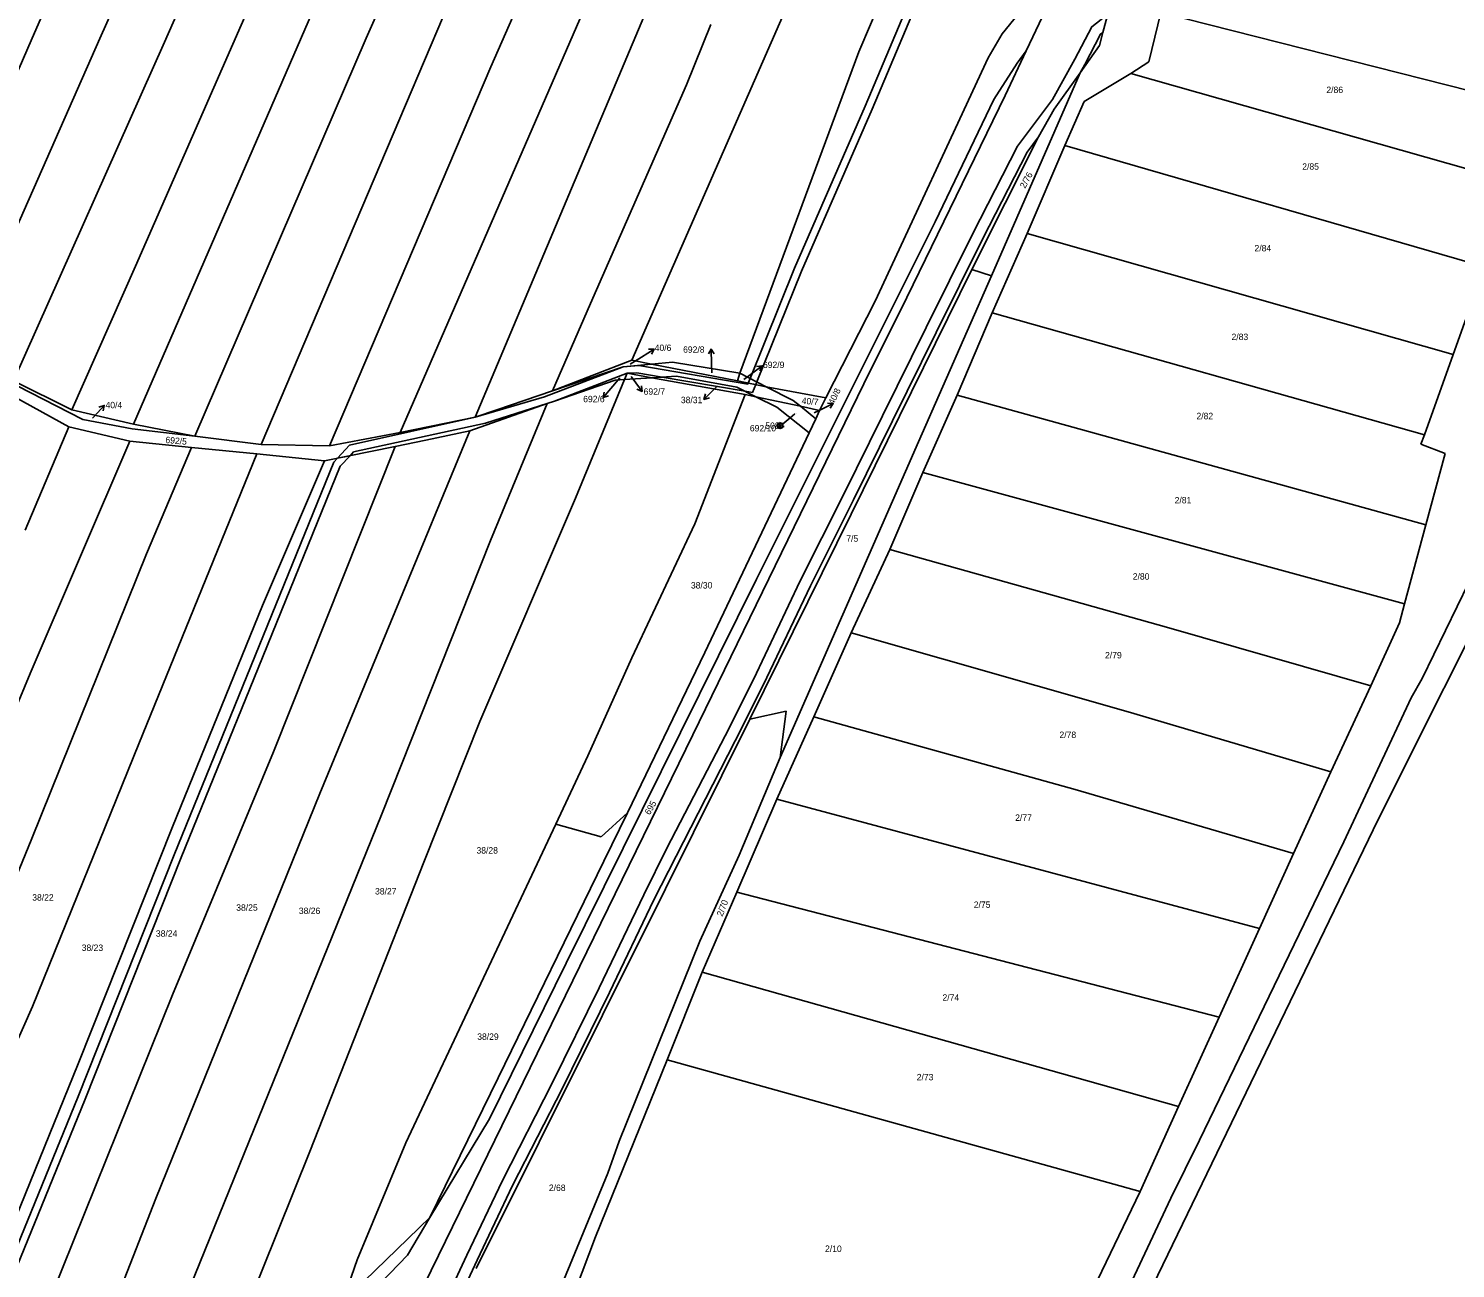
# Model space of a CAD drawing. Extents: x -747333 to -745433, y -1133152 to -1130600.
# Drawn here: x -746124.2 to -745745.7, y -1131253.3 to -1130924.3 of the extents above; entities that cross this region are included whole.
import ezdxf

# ---------------------------------------------------------------- set-up
doc = ezdxf.new("R2010")
doc.units = 0
for name, color, linetype in [('Vrstva 1', 7, 'Continuous'), ('Vrstva 10', 7, 'Continuous'), ('Vrstva 16', 7, 'Continuous'), ('Vrstva 17', 7, 'Continuous'), ('Vrstva 18', 7, 'Continuous'), ('Vrstva 24', 7, 'Continuous'), ('Vrstva 30', 7, 'Continuous'), ('Vrstva 52', 7, 'Continuous'), ('Vrstva 6', 7, 'Continuous')]:
    doc.layers.add(name, color=color, linetype=linetype)

msp = doc.modelspace()

# ---------------------------------------------------------------- linework, layer by layer
at = {"layer": 'Vrstva 1'}
for points in [[(-745848.33, -1130906.51), (-745859.5, -1130930.22)], [(-745865.92, -1130925.72), (-745855.86, -1130913.35)], [(-745839.19, -1130925.32), (-745838.08, -1130921.07)], [(-745869.61, -1130932.09), (-745865.92, -1130925.72)], [(-745840.1, -1130928.8), (-745839.19, -1130925.32)], [(-745859.5, -1130930.22), (-745865.08, -1130942.05)], [(-745845.23, -1130936.04), (-745840.1, -1130928.8)], [(-745899.55, -1130996.61), (-745869.61, -1130932.09)], [(-745852.08, -1130945.69), (-745845.23, -1130936.04)], [(-745865.08, -1130942.05), (-745892.81, -1130998.91)], [(-745856.25, -1130953.03), (-745852.08, -1130945.69)], [(-745873.92, -1130988.21), (-745856.25, -1130953.03)], [(-745905.92, -1131053.19), (-745873.92, -1130988.21)], [(-745746.28, -1131010.82), (-745737.94, -1130987.52)], [(-745766.15, -1131134.13), (-745696.32, -1130994.74)], [(-745912.67, -1131022.25), (-745899.55, -1130996.61)], [(-745892.81, -1130998.91), (-745900.93, -1131015.11)], [(-745753.89, -1131032.06), (-745746.28, -1131010.82)], [(-746109.79, -1131028.02), (-746141.09, -1131012.01)], [(-745966.4, -1131014.05), (-745985.17, -1131020.45)], [(-745958.88, -1131013.33), (-745966.4, -1131014.05)], [(-745953.38, -1131012.81), (-745958.88, -1131013.33)], [(-745935.5, -1131015.73), (-745953.38, -1131012.81)], [(-745968.52, -1131017.59), (-745984.64, -1131023.14)], [(-745966.08, -1131017.43), (-745968.52, -1131017.59)], [(-745958.8, -1131016.95), (-745966.08, -1131017.43)], [(-745952.24, -1131016.51), (-745958.8, -1131016.95)], [(-745936.27, -1131019.43), (-745952.24, -1131016.51)], [(-745900.93, -1131015.11), (-745947.93, -1131111.72)], [(-745928.53, -1131019.33), (-745935.5, -1131015.73)], [(-746113.48, -1131029.98), (-746128.09, -1131021.91)], [(-745985.17, -1131020.45), (-745999.91, -1131025.48)], [(-745931.24, -1131021.98), (-745936.27, -1131019.43)], [(-745925.67, -1131024.8), (-745931.24, -1131021.98)], [(-745921.37, -1131023.03), (-745928.53, -1131019.33)], [(-745914.31, -1131025.61), (-745912.67, -1131022.25)], [(-745986.56, -1131023.8), (-746007.08, -1131031)], [(-745999.91, -1131025.48), (-746005.67, -1131027.4)], [(-745984.64, -1131023.14), (-745986.56, -1131023.8)], [(-745917.09, -1131031.6), (-745925.67, -1131024.8)], [(-745919.43, -1131024.53), (-745921.37, -1131023.03)], [(-745915.31, -1131027.82), (-745919.43, -1131024.53)], [(-745915.31, -1131027.82), (-745914.31, -1131025.61)], [(-746097.27, -1131033.75), (-746113.48, -1131029.98)], [(-746096.65, -1131030.53), (-746109.79, -1131028.02)], [(-746005.67, -1131027.4), (-746025.56, -1131031.47)], [(-745917.09, -1131031.6), (-745915.31, -1131027.82)], [(-746080.96, -1131035.48), (-746097.27, -1131033.75)], [(-746080.02, -1131032.46), (-746096.65, -1131030.53)], [(-746062.49, -1131034.7), (-746080.02, -1131032.46)], [(-746025.56, -1131031.47), (-746044.37, -1131035)], [(-746018.8, -1131033.56), (-746026.94, -1131035.21)], [(-746007.08, -1131031), (-746018.8, -1131033.56)], [(-745944.81, -1131089.83), (-745917.09, -1131031.6)], [(-745754.8, -1131034.61), (-745753.89, -1131032.06)], [(-746063.64, -1131037.14), (-746080.96, -1131035.48)], [(-746045.68, -1131039.01), (-746063.64, -1131037.14)], [(-746044.37, -1131035), (-746062.49, -1131034.7)], [(-746026.94, -1131035.21), (-746045.68, -1131039.01)], [(-745748.38, -1131037.04), (-745754.8, -1131034.61)], [(-745753.49, -1131055.99), (-745748.38, -1131037.04)], [(-745932.85, -1131107.56), (-745905.92, -1131053.19)], [(-745759.13, -1131076.92), (-745753.49, -1131055.99)], [(-745760.51, -1131082.02), (-745759.13, -1131076.92)], [(-745768.13, -1131098.66), (-745760.51, -1131082.02)], [(-745965.24, -1131132.37), (-745944.81, -1131089.83)], [(-745778.72, -1131121.55), (-745768.13, -1131098.66)], [(-745955.19, -1131152.53), (-745932.85, -1131107.56)], [(-745947.93, -1131111.72), (-746021.05, -1131261.49)], [(-745788.57, -1131143.21), (-745778.72, -1131121.55)], [(-745971.56, -1131145.22), (-745965.24, -1131132.37)], [(-745834.96, -1131276.52), (-745766.15, -1131134.13)], [(-745797.62, -1131163.11), (-745788.57, -1131143.21)], [(-745999.59, -1131202.69), (-745971.56, -1131145.22)], [(-746005.43, -1131253.32), (-745955.19, -1131152.53)], [(-745808.32, -1131186.64), (-745797.62, -1131163.11)], [(-745819.11, -1131210.36), (-745808.32, -1131186.64)], [(-746017.69, -1131239.8), (-745999.59, -1131202.69)], [(-745829.33, -1131232.84), (-745819.11, -1131210.36)], [(-745863.16, -1131303.26), (-745829.33, -1131232.84)], [(-746040.86, -1131262.25), (-746017.69, -1131239.8)]]:
    msp.add_lwpolyline(points, dxfattribs=at)
at = {"layer": 'Vrstva 10'}
for points in [[(-745861.91, -1130933.51), (-745859.5, -1130930.22)], [(-745868.13, -1130943.09), (-745861.91, -1130933.51)], [(-745883.67, -1130975.54), (-745868.13, -1130943.09)], [(-745931.04, -1131070.43), (-745883.67, -1130975.54)], [(-745981.51, -1131172.27), (-745931.04, -1131070.43)], [(-746001.9, -1131213.56), (-745981.51, -1131172.27)], [(-746001.9, -1131213.56), (-746017.69, -1131239.8)], [(-746017.69, -1131239.8), (-746023.66, -1131249.74)], [(-746047.28, -1131274.25), (-746023.66, -1131249.74)]]:
    msp.add_lwpolyline(points, dxfattribs=at)
at = {"layer": 'Vrstva 16'}
for p, q in [((-745959.719592, -1131009.38146), (-745958.219738, -1131009.327236)), ((-745943.810475, -1131010.647533), (-745943.089873, -1131009.33101)), ((-745931.037026, -1131013.964605), (-745929.547603, -1131013.779896)), ((-745970.316369, -1131021.717957), (-745971.727607, -1131022.228749)), ((-745961.580478, -1131019.073518), (-745961.409575, -1131020.564588)), ((-745943.551971, -1131022.314521), (-745944.997179, -1131022.719334)), ((-746105.498044, -1131024.753366), (-746104.063095, -1131024.313571)), ((-745912.199622, -1131023.693769), (-745910.701999, -1131023.79188)), ((-745923.721258, -1131029.892673), (-745925.201958, -1131030.137675))]:
    msp.add_line(p, q, dxfattribs=at)
for points in [[(-745961.61, -1131011.45), (-745958.219738, -1131009.327236), (-745958.923555, -1131010.652809)], [(-745943, -1131013.33), (-745943.089873, -1131009.33101), (-745942.310854, -1131010.61383)], [(-745964.58, -1131013.31), (-745961.61, -1131011.45)], [(-745942.95, -1131015.67), (-745943, -1131013.33)], [(-745932.74, -1131016.19), (-745929.547603, -1131013.779896), (-745930.133237, -1131015.161754)], [(-745967.33, -1131017.01), (-745969.15, -1131019.17)], [(-745964.34, -1131016.6), (-745963.79, -1131017.35)], [(-745963.79, -1131017.35), (-745961.409575, -1131020.564588), (-745962.785949, -1131019.966177)], [(-745934.39, -1131017.43), (-745932.74, -1131016.19)], [(-745969.15, -1131019.17), (-745971.727607, -1131022.228749), (-745971.4634, -1131020.751354)], [(-745942.2, -1131019.86), (-745944.997179, -1131022.719334), (-745944.624221, -1131021.265579)], [(-745941.6, -1131019.24), (-745942.2, -1131019.86)], [(-746106.79, -1131027.24), (-746104.063095, -1131024.313571), (-746104.400634, -1131025.775955)], [(-745915.76, -1131026.28), (-745914.29, -1131025.56)], [(-745914.29, -1131025.56), (-745910.701999, -1131023.79188), (-745911.536577, -1131025.039269)], [(-746107.2, -1131027.69), (-746106.79, -1131027.24)], [(-745922.11, -1131027.6), (-745925.201958, -1131030.137675), (-745924.672886, -1131028.733189)], [(-745920.86, -1131026.57), (-745922.11, -1131027.6)]]:
    msp.add_lwpolyline(points, dxfattribs=at)
at = {"layer": 'Vrstva 24'}
msp.add_line((-745924.85, -1131029.67), (-745924.75, -1131029.67), dxfattribs=at)
msp.add_circle((-745924.8, -1131029.67), 0.756017, dxfattribs=at)
at = {"layer": 'Vrstva 30'}
for p, q in [((-745987.33, -1131021.99), (-745966.4, -1131014.05)), ((-745966.4, -1131014.05), (-745962.31, -1131013.66)), ((-745962.31, -1131013.66), (-745933.38, -1131018.64)), ((-745965.38, -1131015.77), (-745984.64, -1131023.14)), ((-745962.77, -1131015.61), (-745965.38, -1131015.77)), ((-745956.05, -1131016.77), (-745962.77, -1131015.61)), ((-745933.38, -1131018.64), (-745933.27, -1131018.37)), ((-746005.67, -1131027.4), (-745987.33, -1131021.99)), ((-745932.12, -1131020.88), (-745934.07, -1131020.54)), ((-745931.27, -1131018.77), (-745932.12, -1131020.88)), ((-745986.56, -1131023.8), (-746002.94, -1131029)), ((-745984.64, -1131023.14), (-745986.56, -1131023.8)), ((-746038.98, -1131034.81), (-746005.67, -1131027.4)), ((-746002.94, -1131029), (-746037.94, -1131036.63)), ((-746042.2, -1131038.3), (-746038.98, -1131034.81)), ((-746037.94, -1131036.63), (-746038.86, -1131037.63))]:
    msp.add_line(p, q, dxfattribs=at)
for points in [[(-745919.16, -1130988.66), (-745930.99, -1131018.06), (-745931.27, -1131018.77), (-745933.27, -1131018.37), (-745932.78, -1131017.14), (-745921, -1130987.88), (-745902.24, -1130944.87), (-745878.06, -1130887.58), (-745853.31, -1130829.15), (-745833.47, -1130782.57), (-745813.85, -1130735.65), (-745786.7, -1130671.43), (-745744.58, -1130691.86), (-745741.56, -1130693.41), (-745742.44, -1130695.2), (-745745.48, -1130693.64), (-745785.68, -1130674.15), (-745812.01, -1130736.43), (-745831.63, -1130783.35), (-745851.47, -1130829.93), (-745876.22, -1130888.36), (-745900.4, -1130945.65), (-745919.16, -1130988.66)], [(-745873.71, -1130978.65), (-745861.81, -1130955.48), (-745852.58, -1130943.08), (-745846.63, -1130932.38), (-745842.15, -1130923.8), (-745837.93, -1130920.58), (-745838.08, -1130921.07), (-745839.19, -1130925.32)], [(-745839.19, -1130925.32), (-745839.79, -1130925.78), (-745843.99, -1130933.8), (-745845.23, -1130936.04), (-745852.08, -1130945.69), (-745856.25, -1130953.03), (-745859.25, -1130957.08)], [(-745859.25, -1130957.08), (-745871.03, -1130980.01), (-745883.4, -1131004.93), (-745894.96, -1131028.36), (-745905.33, -1131049.36)], [(-745931.89, -1131097.05), (-745919.44, -1131070.81), (-745908.01, -1131048.02), (-745897.66, -1131027.04), (-745886.08, -1131003.59), (-745873.71, -1130978.65)], [(-745934.07, -1131020.54), (-745956.05, -1131016.77)], [(-745933.27, -1131018.37), (-745931.27, -1131018.77)], [(-746158.43, -1131330.45), (-746160.82, -1131336.12), (-746161.72, -1131338.25), (-746163.55, -1131337.43), (-746162.67, -1131335.33), (-746160.29, -1131329.69), (-746137.83, -1131273.18), (-746110.98, -1131207.63), (-746085.52, -1131143.54), (-746066.25, -1131096.13), (-746043.18, -1131039.37), (-746042.2, -1131038.3), (-746038.86, -1131037.63), (-746041.46, -1131040.45), (-746064.39, -1131096.89), (-746083.66, -1131144.28), (-746109.12, -1131208.37), (-746135.97, -1131273.92), (-746158.43, -1131330.45)], [(-746038.86, -1131037.63), (-746042.2, -1131038.3)], [(-745905.33, -1131049.36), (-745916.74, -1131072.13), (-745929.19, -1131098.37), (-745936.73, -1131113.3)], [(-745972.78, -1131178.81), (-745960.98, -1131154.13), (-745954.88, -1131141.8), (-745939.41, -1131111.94), (-745931.89, -1131097.05)], [(-745936.73, -1131113.3), (-745958.28, -1131155.45), (-745970.08, -1131180.11), (-745982.56, -1131205.49)], [(-746017.6, -1131270.66), (-746007.86, -1131249.78), (-745998.48, -1131229.96), (-745985.24, -1131204.15), (-745972.78, -1131178.81)], [(-745982.56, -1131205.49), (-745995.78, -1131231.28), (-746005.14, -1131251.06), (-746014.9, -1131271.96)]]:
    msp.add_lwpolyline(points, dxfattribs=at)
at = {"layer": 'Vrstva 52'}
msp.add_lwpolyline([(-745833.56, -1131261), (-745821.19, -1131234.62), (-745813.56, -1131219.25), (-745775.25, -1131140.13), (-745757.44, -1131101.87), (-745754.44, -1131096.75), (-745742.12, -1131071.25)], dxfattribs=at)
at = {"layer": 'Vrstva 6'}
for points in [[(-745954.61, -1130827.58), (-746001.53, -1130934.46)], [(-746105.23, -1130926.97), (-746062.62, -1130831.37)], [(-746088.14, -1130927.89), (-746045.19, -1130830.57)], [(-745994.18, -1130835.79), (-746034.56, -1130926.83)], [(-745900.64, -1130867.39), (-745964.11, -1131012.31)], [(-746025.56, -1131031.47), (-745959.11, -1130878.37)], [(-746123.45, -1130927.43), (-746105.11, -1130885.27)], [(-745888.44, -1130894.11), (-745903.95, -1130930.45)], [(-746059.9, -1130905.32), (-746095.78, -1130987.36)], [(-746024.19, -1130944.61), (-746009.04, -1130908.95)], [(-746096.35, -1131029.25), (-746045.88, -1130913.08)], [(-745960.25, -1130919.53), (-746005.67, -1131027.4)], [(-745823.8, -1130920.07), (-745826.99, -1130933.16)], [(-745722.63, -1130945.73), (-745823.8, -1130920.07)], [(-745949.61, -1130939.2), (-745943.14, -1130923.26)], [(-746157.46, -1131005.59), (-746123.45, -1130927.43)], [(-746141.88, -1131009.81), (-746105.23, -1130926.97)], [(-746034.56, -1130926.83), (-746080.02, -1131032.46)], [(-746128.13, -1131017.8), (-746088.14, -1130927.89)], [(-745903.95, -1130930.45), (-745935.5, -1131015.73)], [(-746001.53, -1130934.46), (-746044.37, -1131035)], [(-745826.99, -1130933.16), (-745831.78, -1130936.25)], [(-745845.23, -1130936.04), (-745868.71, -1130989.88)], [(-745831.78, -1130936.25), (-745844.15, -1130943.62)], [(-745831.78, -1130936.25), (-745729.85, -1130965.15)], [(-745975.07, -1130997.24), (-745949.61, -1130939.2)], [(-746062.49, -1131034.7), (-746024.19, -1130944.61)], [(-745844.15, -1130943.62), (-745849.25, -1130955.31)], [(-745849.25, -1130955.31), (-745859.23, -1130978.67)], [(-745849.25, -1130955.31), (-745737.94, -1130987.52)], [(-745859.23, -1130978.67), (-745868.53, -1130999.77)], [(-745859.23, -1130978.67), (-745746.28, -1131010.82)], [(-746095.78, -1130987.36), (-746112.7, -1131025.49)], [(-745868.71, -1130989.88), (-745873.92, -1130988.21)], [(-745888.07, -1131033.94), (-745868.71, -1130989.88)], [(-745985.17, -1131020.45), (-745975.07, -1130997.24)], [(-745868.53, -1130999.77), (-745877.83, -1131021.56)], [(-745868.53, -1130999.77), (-745753.89, -1131032.06)], [(-745964.11, -1131012.31), (-745985.17, -1131020.45)], [(-745964.11, -1131012.31), (-745958.88, -1131013.33)], [(-745958.88, -1131013.33), (-745936.14, -1131017.79)], [(-746112.7, -1131025.49), (-746128.13, -1131017.8)], [(-745965.38, -1131015.77), (-745984.64, -1131023.14)], [(-745966.08, -1131017.43), (-745979.09, -1131048.94)], [(-745965.38, -1131015.77), (-745966.08, -1131017.43)], [(-745958.8, -1131016.95), (-745965.38, -1131015.77)], [(-745934.1, -1131021.36), (-745958.8, -1131016.95)], [(-745935.5, -1131015.73), (-745936.14, -1131017.79)], [(-745936.14, -1131017.79), (-745928.53, -1131019.33)], [(-745947.42, -1131055.74), (-745934.1, -1131021.36)], [(-745934.1, -1131021.36), (-745931.24, -1131021.98)], [(-745931.24, -1131021.98), (-745919.43, -1131024.53)], [(-745928.53, -1131019.33), (-745912.67, -1131022.25)], [(-745877.83, -1131021.56), (-745886.94, -1131042.08)], [(-745877.83, -1131021.56), (-745753.49, -1131055.99)], [(-746096.35, -1131029.25), (-746112.7, -1131025.49)], [(-745986.56, -1131023.8), (-746001.63, -1131060.16)], [(-745919.43, -1131024.53), (-745914.31, -1131025.61)], [(-746113.48, -1131029.98), (-746125.06, -1131057.44)], [(-746080.02, -1131032.46), (-746096.35, -1131029.25)], [(-746123.7, -1131095.4), (-746097.27, -1131033.75)], [(-746007.08, -1131031), (-746046.86, -1131127.25)], [(-746094.92, -1131114.05), (-746063.64, -1131037.14)], [(-746080.96, -1131035.48), (-746092.84, -1131063.68)], [(-746059.22, -1131116.2), (-746026.94, -1131035.21)], [(-745924.82, -1131117.75), (-745888.07, -1131033.94)], [(-746045.68, -1131039.01), (-746062.14, -1131077.35)], [(-745886.94, -1131042.08), (-745895.67, -1131062.5)], [(-745886.94, -1131042.08), (-745759.13, -1131076.92)], [(-745979.09, -1131048.94), (-746004.47, -1131108.13)], [(-745964.16, -1131091.23), (-745947.42, -1131055.74)], [(-746001.63, -1131060.16), (-746030.57, -1131132.93)], [(-746092.84, -1131063.68), (-746123.3, -1131139.23)], [(-745895.67, -1131062.5), (-745905.99, -1131084.62)], [(-745895.67, -1131062.5), (-745821.65, -1131083.28)], [(-746062.14, -1131077.35), (-746085.94, -1131136.15)], [(-745905.99, -1131084.62), (-745915.82, -1131106.97)], [(-745905.99, -1131084.62), (-745832.47, -1131105.57)], [(-745821.65, -1131083.28), (-745768.13, -1131098.66)], [(-745975.82, -1131117.29), (-745964.16, -1131091.23)], [(-746156.17, -1131173.57), (-746123.7, -1131095.4)], [(-745923.23, -1131105.47), (-745932.85, -1131107.56)], [(-745924.82, -1131117.75), (-745923.23, -1131105.47)], [(-745832.47, -1131105.57), (-745778.72, -1131121.55)], [(-746004.47, -1131108.13), (-746019.32, -1131145.53)], [(-745915.82, -1131106.97), (-745925.69, -1131128.75)], [(-745915.82, -1131106.97), (-745846.49, -1131126.17)], [(-746123.07, -1131183.78), (-746094.92, -1131114.05)], [(-746085.94, -1131180.71), (-746059.22, -1131116.2)], [(-745984.27, -1131135.42), (-745975.82, -1131117.29)], [(-745935.62, -1131143.65), (-745924.82, -1131117.75)], [(-746046.86, -1131127.25), (-746090.39, -1131234.71)], [(-745846.49, -1131126.17), (-745788.57, -1131143.21)], [(-745925.69, -1131128.75), (-745936.27, -1131153.48)], [(-745925.69, -1131128.75), (-745797.62, -1131163.11)], [(-746030.57, -1131132.93), (-746087.87, -1131274.28)], [(-745984.27, -1131135.42), (-746024.09, -1131219.98)], [(-745972.27, -1131138.77), (-745984.27, -1131135.42)], [(-745965.24, -1131132.37), (-745972.27, -1131138.77)], [(-746123.3, -1131139.23), (-746162.26, -1131234.49)], [(-746085.94, -1131136.15), (-746111.01, -1131199.04)], [(-746019.32, -1131145.53), (-746049.56, -1131222.27)], [(-745946.05, -1131166.46), (-745935.62, -1131143.65)], [(-745936.27, -1131153.48), (-745945.5, -1131174.67)], [(-745936.27, -1131153.48), (-745808.32, -1131186.64)], [(-745967.46, -1131219.51), (-745946.05, -1131166.46)], [(-745945.5, -1131174.67), (-745954.75, -1131197.94)], [(-745945.5, -1131174.67), (-745819.11, -1131210.36)], [(-746120.98, -1131267.76), (-746085.94, -1131180.71)], [(-746153.94, -1131253.29), (-746123.07, -1131183.78)], [(-746111.01, -1131199.04), (-746165.85, -1131333.99)], [(-745954.75, -1131197.94), (-745973.74, -1131244.92)], [(-745954.75, -1131197.94), (-745829.33, -1131232.84)], [(-746049.56, -1131222.27), (-746095.99, -1131337.89)], [(-746024.09, -1131219.98), (-746037, -1131251.02)], [(-745970.5, -1131228.02), (-745967.46, -1131219.51)], [(-745982.75, -1131257.85), (-745970.5, -1131228.02)], [(-746090.39, -1131234.71), (-746110.07, -1131284.99)], [(-745973.74, -1131244.92), (-745982.86, -1131269.08)], [(-746037, -1131251.02), (-746040.86, -1131262.25)]]:
    msp.add_lwpolyline(points, dxfattribs=at)

# ---------------------------------------------------------------- texts
at = {"layer": 'Vrstva 16'}
for s, p in [('40/6', (-745958.07, -1131009.86)), ('692/8', (-745950.529961, -1131010.33)), ('692/9', (-745929.35, -1131014.38)), ('692/6', (-745977.032725, -1131023.45)), ('692/7', (-745961, -1131021.46)), ('38/31', (-745951.12019, -1131023.7)), ('40/4', (-746103.74, -1131025.05)), ('692/10', (-745932.820869, -1131031.2))]:
    msp.add_text(s, height=1.7, dxfattribs=at).set_placement(p)
msp.add_text('40/8', height=1.7, rotation=63.94941, dxfattribs=at).set_placement((-745910.6, -1131024.23))
at = {"layer": 'Vrstva 17'}
msp.add_text('508', height=1.7, dxfattribs=at).set_placement((-745928.724596, -1131030.52))
at = {"layer": 'Vrstva 18'}
for s, height, p in [('2/86', 1.7, (-745779.89, -1130941.41)), ('2/85', 1.7, (-745786.29, -1130961.76)), ('2/84', 1.7, (-745798.96, -1130983.42)), ('2/83', 1.7, (-745805.05, -1131006.96)), ('40/6', 0.1, (-745964.58, -1131013.31)), ('692/6', 0.1, (-745967.33, -1131017.01)), ('692/7', 0.1, (-745964.34, -1131016.6)), ('692/8', 0.1, (-745942.95, -1131015.67)), ('692/9', 0.1, (-745934.39, -1131017.43)), ('40/8', 0.1, (-745915.76, -1131026.28)), ('2/82', 1.7, (-745814.35, -1131027.96)), ('692/10', 0.1, (-745920.86, -1131026.57)), ('2/81', 1.7, (-745820.14, -1131050.29)), ('7/5', 1.7, (-745907.24, -1131060.47)), ('38/30', 1.7, (-745948.46, -1131072.88)), ('2/80', 1.7, (-745831.25, -1131070.52)), ('2/79', 1.7, (-745838.6, -1131091.42)), ('2/78', 1.7, (-745850.69, -1131112.54)), ('2/77', 1.7, (-745862.44, -1131134.53)), ('38/28', 1.7, (-746005.34, -1131143.21)), ('38/22', 1.7, (-746123.18, -1131155.7)), ('38/27', 1.7, (-746032.25, -1131154.07)), ('38/25', 1.7, (-746069.07, -1131158.39)), ('38/26', 1.7, (-746052.46, -1131159.25)), ('2/75', 1.7, (-745873.43, -1131157.63)), ('38/24', 1.7, (-746090.38, -1131165.28)), ('38/23', 1.7, (-746110.06, -1131169.05)), ('2/74', 1.7, (-745881.73, -1131182.26)), ('38/29', 1.7, (-746005.14, -1131192.64)), ('2/73', 1.7, (-745888.56, -1131203.38)), ('2/68', 1.7, (-745986.13, -1131232.74)), ('2/10', 1.7, (-745912.88, -1131248.91))]:
    msp.add_text(s, height=height, dxfattribs=at).set_placement(p)
for s, height, rotation, p in [('2/76', 1.7, 61.46757, (-745859.83, -1130966.87)), ('38/31', 0.1, 349.87536, (-745941.6, -1131019.24)), ('40/7', 1.7, 354.57678, (-745919.13, -1131023.85)), ('40/4', 0.1, 352.40535, (-746107.2, -1131027.69)), ('692/5', 1.7, 354.9276, (-746087.91, -1131034.25)), ('695', 1.7, 60.07482, (-745959.4, -1131133.1)), ('2/70', 1.7, 69.14556, (-745940.11, -1131160.04))]:
    msp.add_text(s, height=height, rotation=rotation, dxfattribs=at).set_placement(p)

doc.saveas('drawing.dxf')
